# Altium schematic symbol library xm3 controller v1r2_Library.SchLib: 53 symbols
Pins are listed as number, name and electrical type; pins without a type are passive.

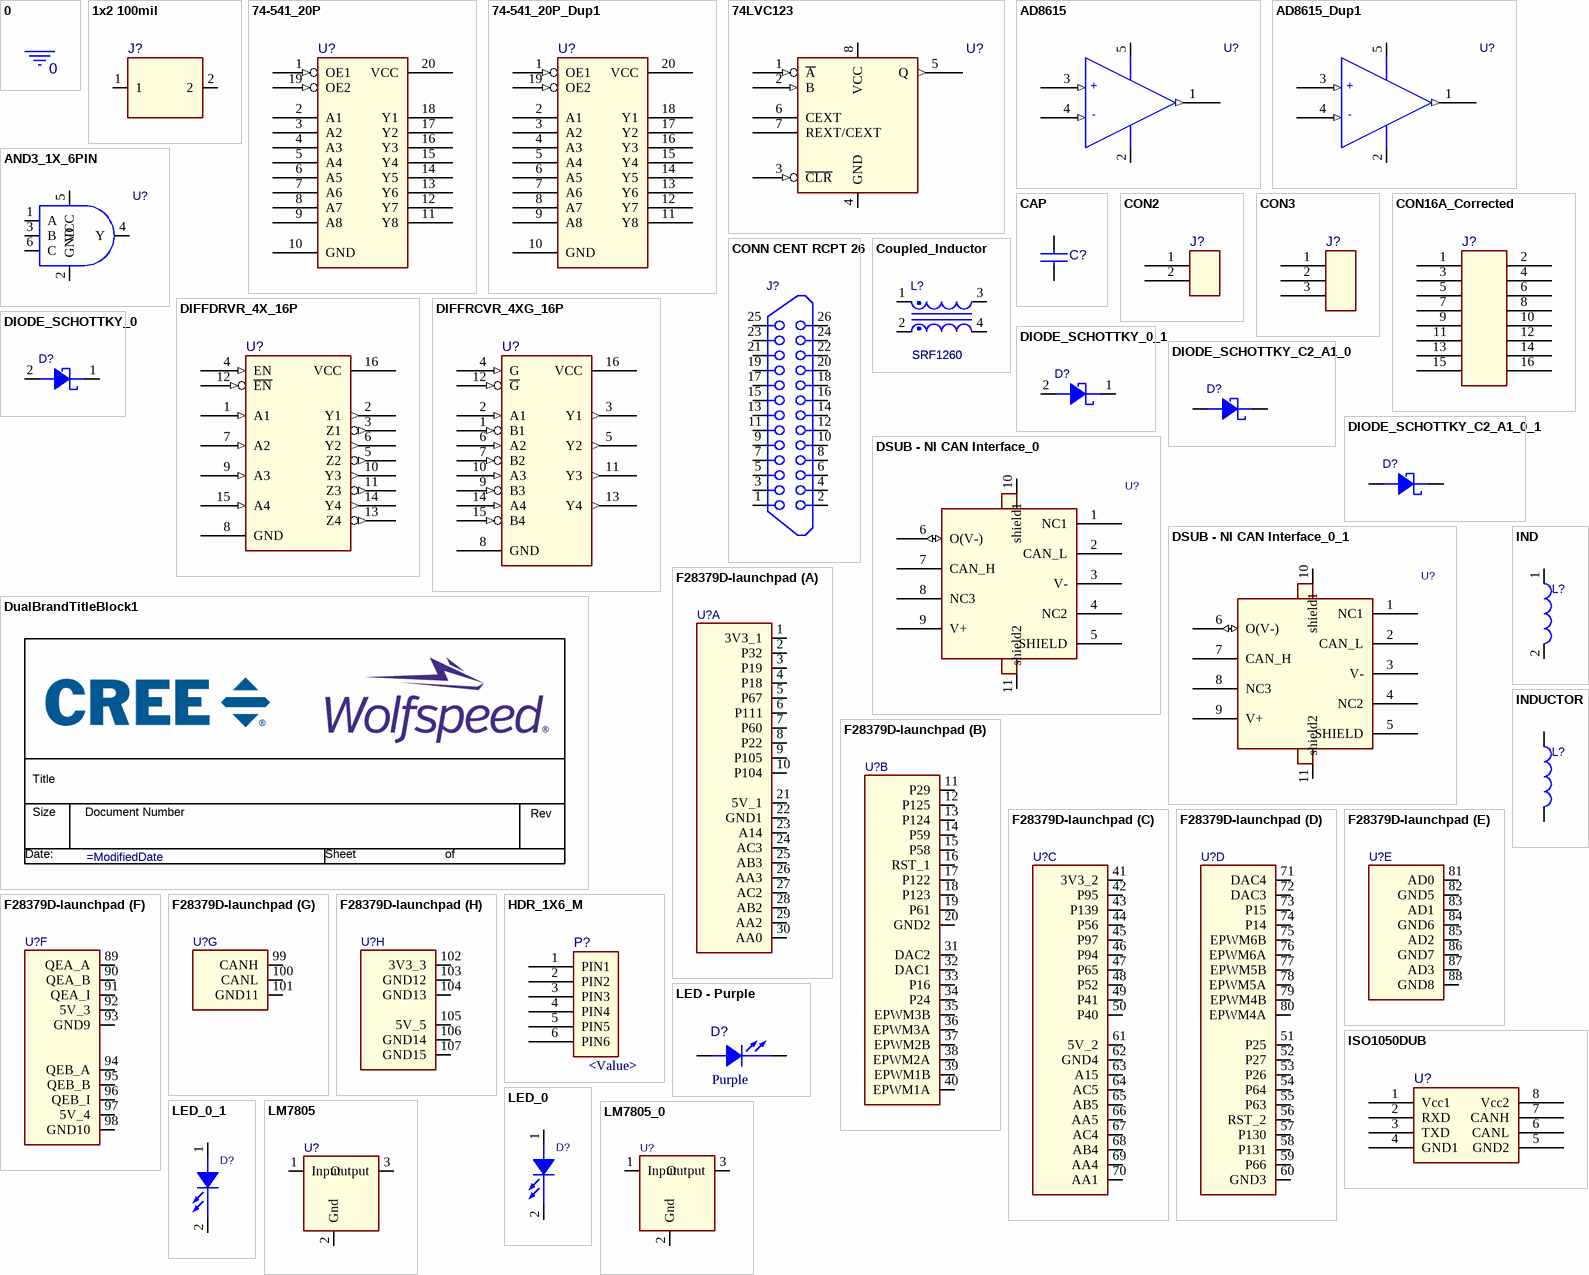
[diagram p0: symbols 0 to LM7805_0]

## 0
designator *  NODENAME: 0  (hidden comment: *)  (graphical)
PSpiceOnly: TRUE
pins: GND (power) hidden to GND

## 1x2 100mil
designator J?
pins: 1, 2

## 74-541_20P
designator U?
pins: 1 OE1 (in), 2 A1 (hiz), 3 A2 (hiz), 4 A3 (hiz), 5 A4 (hiz), 6 A5 (hiz), 7 A6 (hiz), 8 A7 (hiz), 9 A8 (hiz), 10 GND (power), 11 Y8 (hiz), 12 Y7 (hiz), 13 Y6 (hiz), 14 Y5 (hiz), 15 Y4 (hiz), 16 Y3 (hiz), 17 Y2 (hiz), 18 Y1 (hiz), 19 OE2 (in), 20 VCC (power)

## 74-541_20P_Dup1
designator U?
pins: 1 OE1 (in), 2 A1 (hiz), 3 A2 (hiz), 4 A3 (hiz), 5 A4 (hiz), 6 A5 (hiz), 7 A6 (hiz), 8 A7 (hiz), 9 A8 (hiz), 10 GND (power), 11 Y8 (hiz), 12 Y7 (hiz), 13 Y6 (hiz), 14 Y5 (hiz), 15 Y4 (hiz), 16 Y3 (hiz), 17 Y2 (hiz), 18 Y1 (hiz), 19 OE2 (in), 20 VCC (power)

## 74LVC123
designator U?
footprint VSSOP8
pins: 1 ~{A} (in), 2 B (in), 3 ~{CLR} (in), 4 GND (power), 5 Q (out), 6 CEXT, 7 REXT/CEXT, 8 VCC (power)

## AD8615
designator U?
pins: 1 OUT (out), 2 V- (power), 3 IN+ (in), 4 IN- (in), 5 V+ (power)

## AD8615_Dup1
designator U?
pins: 1 OUT (out), 2 V- (power), 3 IN+ (in), 4 IN- (in), 5 V+ (power)

## AND3_1X_6PIN
designator U?
footprint SOT-23-6
pins: 1 A, 2 GND, 3 B, 4 Y, 5 VCC, 6 C

## CAP
designator C?
pins: 1, 2

## CON2
designator J?
pins: 1, 2

## CON3
designator J?
pins: 1, 2, 3

## CON16A_Corrected
designator J?
pins: 1, 2, 3, 4, 5, 6, 7, 8, 9, 10, 11, 12, 13, 14, 15, 16

## CONN CENT RCPT 26
designator J?
pins: 1, 2, 3, 4, 5, 6, 7, 8, 9, 10, 11, 12, 13, 14, 15, 16, 17, 18, 19, 20, 21, 22, 23, 24, 25, 26

## Coupled_Inductor
designator L?, comment SRF1260
Manufacturer: Bourns
footprint SRF1260
pins: 1, 2, 3, 4

## DIFFDRVR_4X_16P
designator U?
pins: 1 A1 (in), 2 Y1 (out), 3 Z1 (out), 4 EN (in), 5 Z2 (out), 6 Y2 (out), 7 A2 (in), 8 GND (power), 9 A3 (in), 10 Y3 (out), 11 Z3 (out), 12 ~{EN} (in), 13 Z4 (out), 14 Y4 (out), 15 A4 (in), 16 VCC (power)

## DIFFRCVR_4XG_16P
designator U?
pins: 1 B1 (in), 2 A1 (in), 3 Y1 (out), 4 G (in), 5 Y2 (out), 6 A2 (in), 7 B2 (in), 8 GND (power), 9 B3 (in), 10 A3 (in), 11 Y3 (out), 12 ~{G} (in), 13 Y4 (out), 14 A4 (in), 15 B4 (in), 16 VCC (power)

## DIODE_SCHOTTKY_0
designator D?
pins: 1 C, 2 A

## DIODE_SCHOTTKY_0_1
designator D?
pins: 1 C, 2 A

## DIODE_SCHOTTKY_C2_A1_0
designator D?
pins: A ANODE, C CATHODE

## DIODE_SCHOTTKY_C2_A1_0_1
designator D?
pins: A ANODE, C CATHODE

## DSUB - NI CAN Interface_0
designator U?
pins: 1 NC1, 2 CAN_L, 3 V-, 4 NC2, 5 SHIELD, 6 O(V-) (io), 7 CAN_H, 8 NC3, 9 V+, 10 shield1, 11 shield2

## DSUB - NI CAN Interface_0_1
designator U?
pins: 1 NC1, 2 CAN_L, 3 V-, 4 NC2, 5 SHIELD, 6 O(V-) (io), 7 CAN_H, 8 NC3, 9 V+, 10 shield1, 11 shield2

## DualBrandTitleBlock1
designator *  (value not drawn)  (graphical)

## F28379D-launchpad
designator U?
part A pins: 1 3V3_1, 2 P32, 3 P19, 4 P18, 5 P67, 6 P111, 7 P60, 8 P22, 9 P105, 10 P104, 21 5V_1, 22 GND1, 23 A14, 24 AC3, 25 AB3, 26 AA3, 27 AC2, 28 AB2, 29 AA2, 30 AA0
part B pins: 11 P29, 12 P125, 13 P124, 14 P59, 15 P58, 16 RST_1, 17 P122, 18 P123, 19 P61, 20 GND2, 31 DAC2, 32 DAC1, 33 P16, 34 P24, 35 EPWM3B, 36 EPWM3A, 37 EPWM2B, 38 EPWM2A, 39 EPWM1B, 40 EPWM1A
part C pins: 41 3V3_2, 42 P95, 43 P139, 44 P56, 45 P97, 46 P94, 47 P65, 48 P52, 49 P41, 50 P40, 61 5V_2, 62 GND4, 63 A15, 64 AC5, 65 AB5, 66 AA5, 67 AC4, 68 AB4, 69 AA4, 70 AA1
part D pins: 51 P25, 52 P27, 53 P26, 54 P64, 55 P63, 56 RST_2, 57 P130, 58 P131, 59 P66, 60 GND3, 71 DAC4, 72 DAC3, 73 P15, 74 P14, 75 EPWM6B, 76 EPWM6A, 77 EPWM5B, 78 EPWM5A, 79 EPWM4B, 80 EPWM4A
part E pins: 81 AD0, 82 GND5, 83 AD1, 84 GND6, 85 AD2, 86 GND7, 87 AD3, 88 GND8
part F pins: 89 QEA_A, 90 QEA_B, 91 QEA_I, 92 5V_3, 93 GND9, 94 QEB_A, 95 QEB_B, 96 QEB_I, 97 5V_4, 98 GND10
part G pins: 99 CANH, 100 CANL, 101 GND11
part H pins: 102 3V3_3, 103 GND12, 104 GND13, 105 5V_5, 106 GND14, 107 GND15

## HDR_1X6_M
designator P?, comment <Value>
pins: 1 PIN1, 2 PIN2, 3 PIN3, 4 PIN4, 5 PIN5, 6 PIN6

## IND
designator L?
pins: 1, 2

## INDUCTOR
designator L?
pins: 1, 2

## ISO1050DUB
designator U?
pins: 1 Vcc1, 2 RXD, 3 TXD, 4 GND1, 5 GND2, 6 CANL, 7 CANH, 8 Vcc2

## LED - Purple
designator D?, comment Purple
Part Number: AA3528VRVFS/A; Manufacturer: Kingbright
footprint D_1409
pins: 1 ANODE, 2 CATHODE

## LED_0
designator D?
pins: 1 A, 2 C

## LED_0_1
designator D?
pins: 1 A, 2 C

## LM7805
designator U?
footprint TO_220_3
pins: 1 Input, 2 Gnd, 3 Output

## LM7805_0
designator U?
footprint TO_220_3
pins: 1 Input, 2 Gnd, 3 Output

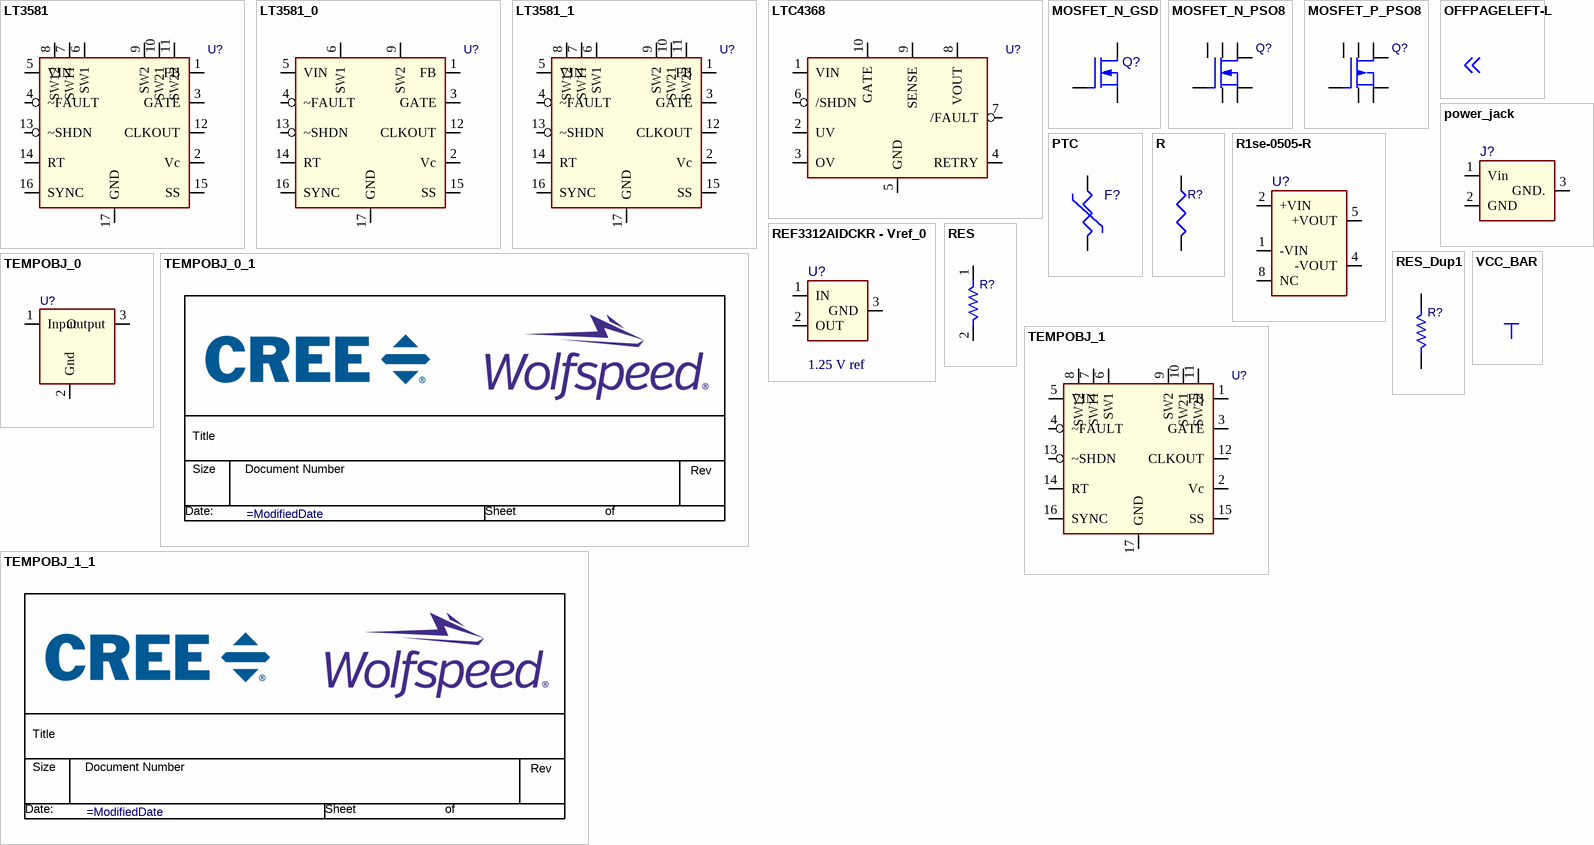
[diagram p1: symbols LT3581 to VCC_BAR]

## LT3581
designator U?
PACK_SHORT: (SW1,SW11,SW12),(SW2,SW21,SW22)
footprint MSOP-16-EP
pins: 1 FB, 2 Vc, 3 GATE, 4 ~FAULT, 5 VIN, 6 SW1 (power), 7 SW11 (power), 8 SW12 (power), 9 SW2 (power), 10 SW21 (power), 11 SW22 (power), 12 CLKOUT, 13 ~SHDN, 14 RT, 15 SS, 16 SYNC, 17 GND

## LT3581_0
designator U?
footprint MSOP-16-EP
pins: 1 FB, 2 Vc, 3 GATE, 4 ~FAULT, 5 VIN, 6 SW1 (power), 7 SW11 (power) hidden, 8 SW12 (power) hidden, 9 SW2 (power), 10 SW21 (power) hidden, 11 SW22 (power) hidden, 12 CLKOUT, 13 ~SHDN, 14 RT, 15 SS, 16 SYNC, 17 GND

## LT3581_1
designator U?
PACK_SHORT: (SW1,SW11,SW12),SW2,SW21,SW22)
footprint MSOP-16-EP
pins: 1 FB, 2 Vc, 3 GATE, 4 ~FAULT, 5 VIN, 6 SW1 (power), 7 SW11 (power), 8 SW12 (power), 9 SW2 (power), 10 SW21 (power), 11 SW22 (power), 12 CLKOUT, 13 ~SHDN, 14 RT, 15 SS, 16 SYNC, 17 GND

## LTC4368
designator U?
footprint MSOP_10
pins: 1 VIN, 2 UV, 3 OV, 4 RETRY, 5 GND, 6 /SHDN, 7 /FAULT, 8 VOUT, 9 SENSE, 10 GATE

## MOSFET_N_GSD
designator Q?
pins: 1 G, 2 S, 3 D

## MOSFET_N_PSO8
designator Q?
PACK_SHORT: (S,S1,S2),(D,D1,D2,D3)
footprint POWER-SO8
pins: 1 S (power), 2 S1 (power), 3 S2 (power), 4 G (power), 5 D (power), 6 D1 (power), 7 D2 (power), 8 D3 (power)

## MOSFET_P_PSO8
designator Q?
PACK_SHORT: (S,S1,S2),(D,D1,D2,D3)
footprint POWER-SO8
pins: 1 S (power), 2 S1 (power), 3 S2 (power), 4 G (power), 5 D (power), 6 D1 (power), 7 D2 (power), 8 D3 (power)

## OFFPAGELEFT-L
designator *  (value not drawn)  (graphical)
pins: $PIN0 (in) hidden

## power_jack
designator J?
footprint powerjack
pins: 1 Vin, 2 GND, 3 GND.

## PTC
designator F?
pins: 1, 2

## R
designator R?
pins: 1, 2

## R1se-0505-R
designator U?
footprint 8-SMD-5leads
pins: 1 -VIN, 2 +VIN, 4 -VOUT, 5 +VOUT, 8 NC

## REF3312AIDCKR - Vref_0
designator U?, comment 1.25 V ref
pins: 1 IN, 2 OUT, 3 GND

## RES
designator R?
pins: 1, 2

## RES_Dup1
designator R?
pins: 1, 2

## TEMPOBJ_0
designator U?
footprint TO_220_3
pins: 1 Input, 2 Gnd, 3 Output

## TEMPOBJ_0_1
designator *  (value not drawn)  (graphical)

## TEMPOBJ_1
designator U?
footprint MSOP-16-EP
pins: 1 FB, 2 Vc, 3 GATE, 4 ~FAULT, 5 VIN, 6 SW1, 7 SW11, 8 SW12, 9 SW2, 10 SW21, 11 SW22, 12 CLKOUT, 13 ~SHDN, 14 RT, 15 SS, 16 SYNC, 17 GND

## TEMPOBJ_1_1
designator *  (value not drawn)  (graphical)

## VCC_BAR
designator *  (value not drawn)  (graphical)
pins: $PIN0 (power) hidden to $PIN0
